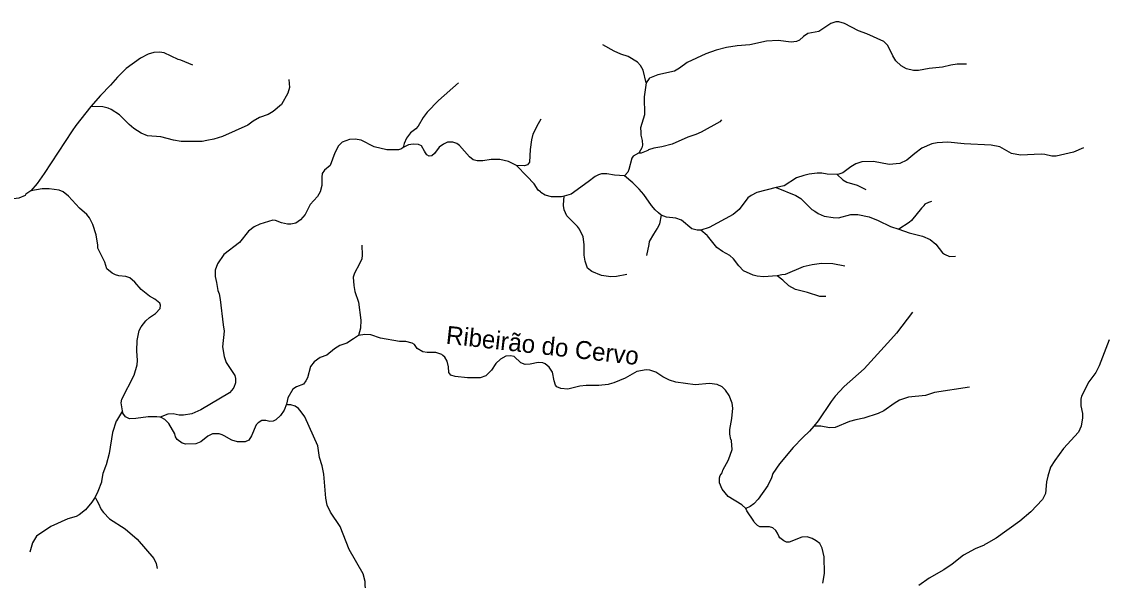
# Model space of a CAD drawing. Extents: x 396 to 422.2, y 7649.8 to 7677.6.
# Drawn here: x 416.1 to 422.16, y 7653.05 to 7656.16 of the extents above; entities that cross this region are included whole.
import ezdxf
from ezdxf.enums import TextEntityAlignment as Align

# ---------------------------------------------------------------- set-up
doc = ezdxf.new("R2010")
doc.units = 0
doc.header["$LTSCALE"] = 0.032
doc.layers.add('61', color=7, linetype='Continuous')
doc.layers.add('7', color=7, linetype='Continuous', lineweight=25)

msp = doc.modelspace()

# ---------------------------------------------------------------- linework, layer by layer
at = {"layer": '7'}
for points in [[(421.3641, 7655.9202), (421.3118, 7655.9193), (421.2763, 7655.9144), (421.2292, 7655.9026), (421.1555, 7655.8948), (421.0965, 7655.8842), (421.0678, 7655.8835), (421.0296, 7655.8938), (420.999, 7655.9106), (420.9703, 7655.9374), (420.9528, 7655.9657), (420.9263, 7656.0235), (420.9038, 7656.0461), (420.8085, 7656.0891), (420.7617, 7656.104), (420.6848, 7656.1465), (420.6522, 7656.1554), (420.6367, 7656.1553), (420.609, 7656.146), (420.5418, 7656.102), (420.4795, 7656.09), (420.4567, 7656.0742), (420.4339, 7656.0538), (420.4176, 7656.0458), (420.3882, 7656.0414), (420.3145, 7656.0509), (420.2503, 7656.0478), (420.1581, 7656.0279), (420.086, 7656.0223), (420.0278, 7656.0126), (419.97, 7655.9973), (419.913, 7655.9766), (419.8083, 7655.9283), (419.7668, 7655.8974), (419.7382, 7655.8812), (419.6446, 7655.8593), (419.5983, 7655.8408), (419.5979, 7655.8402), (419.5811, 7655.8164), (419.5811, 7655.8163)], [(417.056, 7655.9146), (416.9906, 7655.9421), (416.9757, 7655.9447), (416.8969, 7655.9825), (416.8721, 7655.9855), (416.8398, 7655.9839), (416.8076, 7655.975), (416.7659, 7655.9522), (416.6854, 7655.8948), (416.637, 7655.8473), (416.5995, 7655.8019), (416.5434, 7655.7442), (416.49, 7655.6831)], [(419.5811, 7655.8163), (419.5639, 7655.8869), (419.5484, 7655.9119), (419.5329, 7655.9305), (419.48, 7655.9629), (419.4397, 7655.9749), (419.4016, 7655.991), (419.3384, 7656.0279)], [(417.5919, 7655.8349), (417.595, 7655.7894), (417.5862, 7655.7574), (417.5509, 7655.6942), (417.5036, 7655.6563), (417.4759, 7655.6401), (417.4286, 7655.6227), (417.3928, 7655.6019), (417.3632, 7655.5791), (417.2217, 7655.5161), (417.1745, 7655.5025), (417.1342, 7655.4945), (417.1096, 7655.4896), (416.9926, 7655.4896), (416.9495, 7655.4967), (416.8784, 7655.5142), (416.805, 7655.5202), (416.7692, 7655.5354), (416.7286, 7655.562), (416.7018, 7655.5844), (416.6478, 7655.6384), (416.6028, 7655.6678), (416.5858, 7655.6754), (416.5555, 7655.6817), (416.49, 7655.6831)], [(418.5361, 7655.8149), (418.536, 7655.8148), (418.4236, 7655.7167), (418.3607, 7655.6517), (418.3392, 7655.6222), (418.3117, 7655.5746), (418.2974, 7655.5594), (418.2687, 7655.5371), (418.2458, 7655.507), (418.2332, 7655.4771), (418.228, 7655.4551)], [(419.5811, 7655.8163), (419.5696, 7655.738), (419.5719, 7655.6371), (419.5497, 7655.566), (419.5501, 7655.5418), (419.5504, 7655.5238), (419.5584, 7655.4943), (419.5607, 7655.4696), (419.5554, 7655.4531), (419.5412, 7655.4273), (419.5374, 7655.425)], [(416.49, 7655.6831), (416.4051, 7655.5788), (416.3851, 7655.5483), (416.23, 7655.3118), (416.1903, 7655.2556), (416.1553, 7655.2138)], [(418.9947, 7655.6132), (418.9785, 7655.5881), (418.9496, 7655.5296), (418.9419, 7655.4976), (418.9348, 7655.4445), (418.9307, 7655.3733), (418.9195, 7655.3596), (418.9035, 7655.3543), (418.859, 7655.3552)], [(420.0003, 7655.61), (419.9899, 7655.598), (419.8866, 7655.5407), (419.8562, 7655.5272), (419.8117, 7655.5141), (419.7258, 7655.4746), (419.6684, 7655.4585), (419.6239, 7655.4518), (419.5939, 7655.4425), (419.5897, 7655.4381), (419.5529, 7655.4235), (419.5374, 7655.425)], [(418.228, 7655.4551), (418.2191, 7655.4479), (418.2009, 7655.4428), (418.1369, 7655.4432), (418.066, 7655.4585), (417.9938, 7655.4968), (417.9596, 7655.5022), (417.9291, 7655.5006), (417.8875, 7655.4853), (417.868, 7655.4642), (417.8469, 7655.4254), (417.8205, 7655.355), (417.7907, 7655.3301), (417.7777, 7655.3114), (417.7742, 7655.2912)], [(418.859, 7655.3552), (418.8134, 7655.3783), (418.7657, 7655.3889), (418.7171, 7655.3882), (418.6715, 7655.3811), (418.6389, 7655.3811), (418.6182, 7655.3867), (418.5963, 7655.4045), (418.541, 7655.4677), (418.5257, 7655.4783), (418.5033, 7655.4855), (418.4746, 7655.4855), (418.4522, 7655.4747), (418.4287, 7655.4569), (418.4015, 7655.4224), (418.3879, 7655.4096), (418.3732, 7655.4082), (418.3603, 7655.4149), (418.3516, 7655.4256), (418.3459, 7655.4359), (418.3297, 7655.4653), (418.3135, 7655.4719), (418.2835, 7655.4744), (418.2583, 7655.4704), (418.228, 7655.4551)], [(422.0151, 7655.4544), (421.9593, 7655.4303), (421.8632, 7655.4082), (421.8393, 7655.4066), (421.7986, 7655.4169), (421.7791, 7655.4186), (421.6642, 7655.4122), (421.6134, 7655.4225), (421.5485, 7655.459), (421.5007, 7655.4687), (421.3514, 7655.4769), (421.2587, 7655.4863), (421.2002, 7655.4823), (421.1711, 7655.4757), (421.1146, 7655.4514), (421.0756, 7655.4228), (421.0316, 7655.3846), (420.9923, 7655.3661), (420.9334, 7655.3604), (420.8452, 7655.3778), (420.7804, 7655.3761), (420.7479, 7655.3643), (420.7204, 7655.3475), (420.6759, 7655.3142), (420.6468, 7655.3048), (420.6429, 7655.305)], [(419.5374, 7655.425), (419.5077, 7655.4072), (419.5001, 7655.3967), (419.4841, 7655.3329), (419.4777, 7655.3186), (419.4594, 7655.2972)], [(419.1245, 7655.1857), (419.1082, 7655.1809), (419.054, 7655.1816), (419.0182, 7655.1906), (418.9934, 7655.2046), (418.9927, 7655.2081), (418.9798, 7655.2174), (418.9576, 7655.2527), (418.9162, 7655.2957), (418.859, 7655.3552)], [(417.7742, 7655.2912), (417.7744, 7655.2435), (417.7664, 7655.2087), (417.7504, 7655.1826), (417.7109, 7655.1381), (417.6813, 7655.083), (417.6567, 7655.0527), (417.6303, 7655.0339), (417.6026, 7655.0286), (417.5832, 7655.0288), (417.5509, 7655.0369), (417.5168, 7655.0494), (417.5023, 7655.0507), (417.4296, 7655.0292), (417.3983, 7655.0151), (417.3675, 7654.9908), (417.3169, 7654.9275), (417.2295, 7654.8608), (417.1935, 7654.8077), (417.1812, 7654.7733), (417.1811, 7654.7386), (417.1878, 7654.705), (417.1967, 7654.6599), (417.2035, 7654.6422), (417.2098, 7654.6094), (417.2257, 7654.4691), (417.2321, 7654.4336), (417.2218, 7654.3463), (417.2306, 7654.2929), (417.2427, 7654.2595), (417.2909, 7654.1868), (417.2943, 7654.1704), (417.2942, 7654.1455), (417.2847, 7654.1211), (417.2746, 7654.1053), (417.2606, 7654.0906), (417.1016, 7653.9966), (417.0507, 7653.9728), (417.0054, 7653.9654), (416.9801, 7653.967), (416.9466, 7653.9734), (416.9182, 7653.9722), (416.8759, 7653.9546)], [(419.4594, 7655.2972), (419.4049, 7655.3012), (419.3622, 7655.31), (419.3325, 7655.3086), (419.3152, 7655.3044), (419.2973, 7655.2952), (419.2583, 7655.264), (419.1621, 7655.1969), (419.1245, 7655.1857)], [(419.6643, 7655.0795), (419.6486, 7655.0925), (419.6297, 7655.1096), (419.6096, 7655.1335), (419.5669, 7655.1946), (419.5423, 7655.2234), (419.5056, 7655.2593), (419.4594, 7655.2972)], [(420.6429, 7655.305), (420.5875, 7655.3078), (420.5577, 7655.3125), (420.5315, 7655.3124), (420.487, 7655.3072), (420.4583, 7655.3006), (420.4176, 7655.2863), (420.349, 7655.2432), (420.3039, 7655.2322)], [(420.6429, 7655.305), (420.6752, 7655.2761), (420.6965, 7655.2622), (420.7541, 7655.2457), (420.8026, 7655.2224)], [(416.1553, 7655.2138), (416.1271, 7655.1953), (416.1233, 7655.1895), (416.0889, 7655.1738), (416.0187, 7655.165), (415.966, 7655.1467), (415.9134, 7655.114), (415.8804, 7655.1068), (415.8604, 7655.1083), (415.8232, 7655.1228), (415.8159, 7655.13)], [(416.6621, 7654.056), (416.7296, 7654.1892), (416.7463, 7654.2462), (416.7489, 7654.2701), (416.7456, 7654.3235), (416.7465, 7654.3813), (416.7582, 7654.4376), (416.7685, 7654.4582), (416.7949, 7654.4916), (416.8161, 7654.5103), (416.8484, 7654.5315), (416.8751, 7654.559), (416.8764, 7654.5787), (416.8734, 7654.59), (416.845, 7654.6124), (416.8158, 7654.6281), (416.7686, 7654.6659), (416.7337, 7654.7071), (416.7064, 7654.7296), (416.6842, 7654.7373), (416.6456, 7654.7414), (416.6257, 7654.7472), (416.6075, 7654.7568), (416.5785, 7654.7812), (416.5669, 7654.8168), (416.5289, 7654.8963), (416.5287, 7654.9125), (416.5181, 7654.9703), (416.4999, 7655.0273), (416.4819, 7655.0649), (416.4663, 7655.0837), (416.4269, 7655.1184), (416.3649, 7655.1843), (416.3353, 7655.2097), (416.3125, 7655.2182), (416.258, 7655.2263), (416.219, 7655.2255), (416.1553, 7655.2138)], [(420.3039, 7655.2322), (420.1969, 7655.2062), (420.1644, 7655.1894), (420.146, 7655.175), (420.0989, 7655.1113), (420.0655, 7655.0832), (419.9317, 7655.0099), (419.8847, 7654.9966)], [(420.3039, 7655.2322), (420.4128, 7655.1879), (420.4409, 7655.1723), (420.5021, 7655.1112), (420.5188, 7655.1007), (420.5381, 7655.0885), (420.5721, 7655.074), (420.6208, 7655.0653), (420.6506, 7655.0637), (420.7196, 7655.0827), (420.7579, 7655.0834), (420.8213, 7655.0699), (420.8723, 7655.0499), (420.94, 7655.0168), (420.9861, 7655.0009)], [(419.4724, 7654.7495), (419.4148, 7654.7375), (419.3833, 7654.7368), (419.3314, 7654.7438), (419.2788, 7654.7652), (419.2546, 7654.7848), (419.2406, 7654.8231), (419.2355, 7654.856), (419.2354, 7654.9157), (419.2291, 7654.958), (419.2089, 7655.0017), (419.1977, 7655.0161), (419.1396, 7655.0752), (419.1235, 7655.1096), (419.12, 7655.1324), (419.1204, 7655.1369), (419.1245, 7655.1857)], [(421.1695, 7655.1554), (421.1523, 7655.1504), (421.1317, 7655.1399), (421.1258, 7655.1331), (421.1283, 7655.1327), (421.1127, 7655.1184), (421.0582, 7655.0498), (421.0436, 7655.0377), (420.9861, 7655.0009)], [(419.6643, 7655.0795), (419.6548, 7655.0314), (419.6407, 7655.0033), (419.6402, 7655.0026), (419.6203, 7654.9738), (419.5976, 7654.9333), (419.5959, 7654.9153), (419.5816, 7654.854)], [(419.8847, 7654.9966), (419.8636, 7654.995), (419.8337, 7655.0023), (419.7778, 7655.0511), (419.7455, 7655.0621), (419.6932, 7655.0677), (419.6643, 7655.0795)], [(420.3092, 7654.7408), (420.2331, 7654.7367), (420.1976, 7654.7398), (420.176, 7654.7461), (420.1228, 7654.7691), (420.0962, 7654.7974), (420.0662, 7654.8358), (420.0455, 7654.8548), (420.0056, 7654.8764), (419.9742, 7654.8999), (419.9211, 7654.9641), (419.9195, 7654.9656), (419.8847, 7654.9966)], [(420.9861, 7655.0009), (421.0445, 7654.9808), (421.1188, 7654.9632), (421.1617, 7654.9446), (421.1931, 7654.9187), (421.2306, 7654.8704), (421.2402, 7654.8623), (421.2689, 7654.8493), (421.3018, 7654.8516)], [(417.9978, 7654.9114), (417.9994, 7654.8561), (417.9969, 7654.8371), (417.9846, 7654.8077), (417.9563, 7654.7571), (417.9499, 7654.735), (417.9538, 7654.6873), (417.9595, 7654.655), (417.9786, 7654.5947), (417.9921, 7654.4946), (417.9897, 7654.4496), (417.9783, 7654.4089)], [(420.6862, 7654.7949), (420.6203, 7654.8092), (420.5558, 7654.81), (420.5047, 7654.8036), (420.4534, 7654.7922), (420.3542, 7654.7497), (420.3358, 7654.7463), (420.3092, 7654.7408)], [(420.5809, 7654.6267), (420.5466, 7654.6259), (420.4791, 7654.6486), (420.4122, 7654.6664), (420.3747, 7654.6864), (420.3416, 7654.7183), (420.3092, 7654.7408)], [(421.0626, 7654.5397), (420.9738, 7654.423), (420.9421, 7654.3881), (420.7935, 7654.2244), (420.6823, 7654.1259), (420.6316, 7654.0721), (420.6095, 7654.0432), (420.5385, 7653.9343), (420.5141, 7653.9059)], [(419.6339, 7654.2049), (419.6015, 7654.216), (419.5812, 7654.2182), (419.5286, 7654.2086), (419.4635, 7654.1728), (419.4011, 7654.1462), (419.3738, 7654.1385), (419.3692, 7654.1372), (419.3176, 7654.1314), (419.2463, 7654.1313), (419.2115, 7654.1273), (419.1437, 7654.111), (419.1062, 7654.1147), (419.084, 7654.1234), (419.0755, 7654.1335), (419.0678, 7654.1569), (419.0585, 7654.2052), (419.0407, 7654.2326), (419.0174, 7654.2527), (419.0058, 7654.2582), (418.9786, 7654.2589), (418.9343, 7654.2498), (418.9069, 7654.2486), (418.883, 7654.2574), (418.8449, 7654.2922), (418.8259, 7654.2956), (418.8001, 7654.294), (418.7696, 7654.277), (418.7437, 7654.2536), (418.72, 7654.2165), (418.6886, 7654.1843), (418.6562, 7654.1744), (418.5855, 7654.1737), (418.5165, 7654.1816), (418.4923, 7654.1888), (418.4816, 7654.2038), (418.4793, 7654.235), (418.473, 7654.2661), (418.4605, 7654.2895), (418.4489, 7654.2991), (418.4435, 7654.3036), (418.4094, 7654.3141), (418.3622, 7654.3148), (418.3364, 7654.3181), (418.3056, 7654.338), (418.2909, 7654.3588), (418.2776, 7654.3666), (418.2422, 7654.3753), (418.2071, 7654.3753), (418.1014, 7654.3945), (418.0485, 7654.4129), (418.0134, 7654.4152), (417.9783, 7654.4089)], [(417.9783, 7654.4089), (417.9517, 7654.3916), (417.9135, 7654.3668), (417.8747, 7654.3536), (417.8462, 7654.3355), (417.8028, 7654.3004), (417.7665, 7654.2876), (417.7329, 7654.2629), (417.712, 7654.2368), (417.6946, 7654.1749), (417.6862, 7654.157), (417.6724, 7654.1395), (417.6336, 7654.1236), (417.6134, 7654.1114), (417.5864, 7654.0623), (417.5829, 7654.044), (417.5775, 7654.028)], [(422.1581, 7654.3849), (422.1015, 7654.2403), (422.0833, 7654.2046), (422.0441, 7654.151), (422.0034, 7654.0711), (421.9996, 7654.0547), (421.9996, 7654.0186), (422.0091, 7653.9758), (422.0091, 7653.9511), (422.0013, 7653.9048), (421.987, 7653.8724), (421.9036, 7653.7805), (421.8544, 7653.7149), (421.8319, 7653.6769), (421.8158, 7653.6268), (421.8097, 7653.5959), (421.8027, 7653.5301), (421.7863, 7653.4973), (421.721, 7653.4277), (421.6596, 7653.3759), (421.5287, 7653.2826), (421.4735, 7653.2495), (421.4648, 7653.247), (421.4616, 7653.2428), (421.4123, 7653.2221), (421.3459, 7653.1881), (421.2836, 7653.138), (421.2364, 7653.1057), (421.1561, 7653.0589), (421.0975, 7653.0184)], [(420.1355, 7653.447), (420.1124, 7653.4673), (420.0375, 7653.5129), (420.0039, 7653.5549), (419.9884, 7653.5902), (419.9893, 7653.6177), (419.9931, 7653.6313), (420.0026, 7653.6458), (420.0078, 7653.6607), (420.0392, 7653.7171), (420.0584, 7653.7748), (420.0555, 7653.8229), (420.0552, 7653.828), (420.0522, 7653.8302), (420.0459, 7653.8597), (420.0457, 7653.8866), (420.0568, 7653.9468), (420.0632, 7654.0049), (420.0599, 7654.0335), (420.0415, 7654.0751), (420.0215, 7654.1053), (420.0041, 7654.1233), (419.9759, 7654.136), (419.932, 7654.1417), (419.8529, 7654.1342), (419.7455, 7654.1506), (419.7104, 7654.1618), (419.6733, 7654.1788), (419.6339, 7654.2049)], [(421.38, 7654.1227), (421.1854, 7654.0928), (421.1359, 7654.0754), (421.0408, 7654.0661), (420.9902, 7654.0493), (420.9603, 7654.032), (420.9025, 7653.9912), (420.8712, 7653.9755), (420.7929, 7653.9497), (420.7471, 7653.9396), (420.7117, 7653.9317), (420.6323, 7653.8976), (420.6011, 7653.8961), (420.5529, 7653.9056), (420.5141, 7653.9059)], [(416.6655, 7653.9907), (416.6581, 7654.0342), (416.6621, 7654.056)], [(416.6655, 7653.9907), (416.6323, 7653.9345), (416.6292, 7653.9332), (416.6094, 7653.87), (416.5908, 7653.7534), (416.5742, 7653.6903), (416.5724, 7653.6856), (416.5706, 7653.6808), (416.5558, 7653.6422), (416.5483, 7653.5981), (416.5476, 7653.5939), (416.5285, 7653.5407), (416.5137, 7653.5104)], [(416.8759, 7653.9546), (416.857, 7653.957), (416.8076, 7653.9575), (416.739, 7653.9471), (416.7046, 7653.9456), (416.6823, 7653.9579), (416.6677, 7653.9775), (416.6655, 7653.9907)], [(417.5775, 7654.028), (417.5662, 7653.9942), (417.5458, 7653.9642), (417.519, 7653.9404), (417.5049, 7653.9328), (417.4857, 7653.9312), (417.4626, 7653.9374), (417.4402, 7653.9363), (417.4198, 7653.9242), (417.4086, 7653.9116), (417.3838, 7653.8518), (417.3679, 7653.8278), (417.3483, 7653.8179), (417.3052, 7653.818), (417.2733, 7653.8277), (417.2305, 7653.8513), (417.22, 7653.8571), (417.2034, 7653.8626), (417.1657, 7653.8627), (417.1403, 7653.8494), (417.1015, 7653.8184), (417.0741, 7653.806), (417.0177, 7653.8053), (416.9982, 7653.8113), (416.9706, 7653.8308), (416.9611, 7653.8459), (416.9559, 7653.8633), (416.9241, 7653.9203), (416.9014, 7653.943), (416.8808, 7653.954), (416.8759, 7653.9546)], [(418.0863, 7652.7787), (418.0732, 7652.8149), (418.0663, 7652.8259), (418.0341, 7652.9133), (418.0263, 7652.9485), (418.0185, 7652.9834), (418.017, 7653.0399), (418.0058, 7653.0839), (417.9268, 7653.218), (417.877, 7653.3465), (417.8226, 7653.4269), (417.805, 7653.4647), (417.797, 7653.5053), (417.7855, 7653.6384), (417.776, 7653.6843), (417.7627, 7653.7305), (417.7523, 7653.7949), (417.6797, 7653.9564), (417.6607, 7653.9853), (417.6456, 7654.0025), (417.6264, 7654.0156), (417.603, 7654.0244), (417.5863, 7654.0245), (417.5775, 7654.028)], [(420.5141, 7653.9059), (420.4898, 7653.8775), (420.4517, 7653.8427), (420.398, 7653.7866), (420.3223, 7653.6947), (420.2853, 7653.6412), (420.2783, 7653.6168), (420.2572, 7653.5742), (420.2042, 7653.4996), (420.1795, 7653.4724), (420.1599, 7653.4583), (420.1355, 7653.447)], [(416.5137, 7653.5104), (416.4946, 7653.4818), (416.4592, 7653.439), (416.4238, 7653.4114), (416.4069, 7653.4032), (416.361, 7653.3887), (416.2657, 7653.3474), (416.1875, 7653.2924), (416.1639, 7653.2559), (416.1492, 7653.2047)], [(416.5137, 7653.5104), (416.5224, 7653.4911), (416.5303, 7653.4786), (416.5472, 7653.4411), (416.5587, 7653.4238), (416.5932, 7653.3899), (416.68, 7653.333), (416.7462, 7653.2759), (416.8392, 7653.1678), (416.8525, 7653.1408), (416.859, 7653.1138)], [(420.5639, 7653.0309), (420.5733, 7653.0858), (420.5712, 7653.1787), (420.5604, 7653.2255), (420.5464, 7653.2515), (420.5274, 7653.2676), (420.5043, 7653.2799), (420.4763, 7653.2884), (420.4476, 7653.2868), (420.3759, 7653.2597), (420.3616, 7653.2597), (420.3466, 7653.2667), (420.3235, 7653.2835), (420.3185, 7653.2935), (420.3122, 7653.3104), (420.3025, 7653.3251), (420.2849, 7653.3386), (420.2674, 7653.3442), (420.2126, 7653.3443), (420.2007, 7653.3515), (420.1812, 7653.3701), (420.1798, 7653.3758), (420.1413, 7653.4344), (420.1355, 7653.447)]]:
    msp.add_lwpolyline(points, dxfattribs=at)

# ---------------------------------------------------------------- texts
at = {"layer": '61'}
msp.add_text('Ribeirão do Cervo', height=0.1, rotation=353.624, dxfattribs=at).set_placement((418.998, 7654.3048), align=Align.CENTER)

doc.saveas('drawing.dxf')
